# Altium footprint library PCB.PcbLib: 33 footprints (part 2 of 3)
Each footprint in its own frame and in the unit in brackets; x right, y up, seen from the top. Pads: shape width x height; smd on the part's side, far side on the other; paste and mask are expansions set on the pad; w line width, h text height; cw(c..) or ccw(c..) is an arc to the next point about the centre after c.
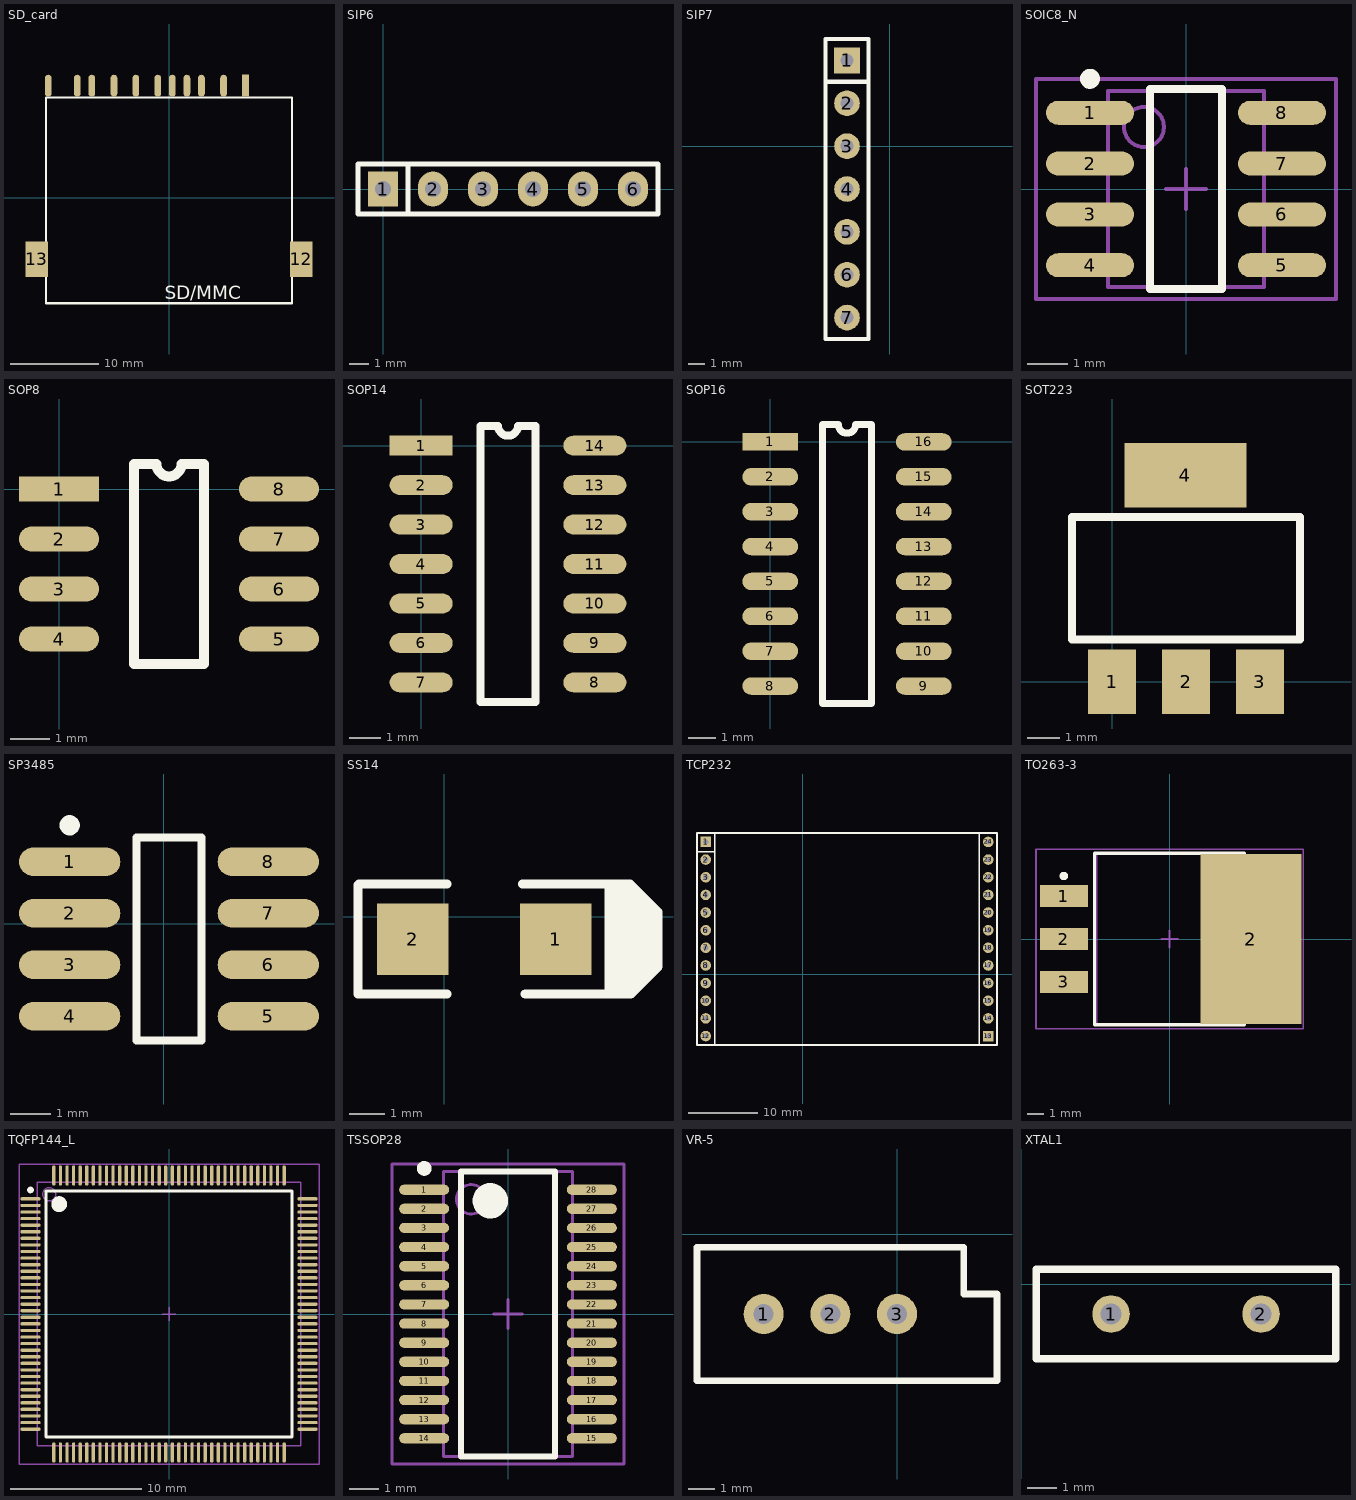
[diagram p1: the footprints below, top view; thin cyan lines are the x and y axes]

## SD_card [mil]
height 62.99
pads (13):
  oval 30x98.43 smd: 1(244,500) 2(145,500) 3(15,500) 3(80,500) 4(-50,500) 5(-148,500) 6(-246,500) 7(-345,500) 8(-410,500) 10(-540,500)
  rect 30x98.43 smd: 9(342,500)
  rect 100x160 smd: 12(590.55,-275.59) 13(-590.55,-275.59)
Top Overlay:
  lines w10: -550,-472.44 550,-472.44 550,447.56 -550,447.56 -550,-472.44
  text "SD/MMC" at -20,-455 h60

## SIP6 [mil]
pads (6):
  rect 60x70 hole 32: 1(0,0)
  oval 60x70 hole 32: 2(100,0) 3(200,0) 4(300,0) 5(400,0) 6(500,0)
Top Overlay:
  lines w10: 50,-50 50,50 ; -50,-50 550,-50 550,50 -50,50 -50,-50

## SIP7 [mil]
height 62.99
pads (7):
  rect 60x60 hole 30: 1(-100,200)
  round 60 hole 30: 2(-100,100) 3(-100,0) 4(-100,-100) 5(-100,-200) 6(-100,-300) 7(-100,-400)
Top Overlay:
  lines w10: -150,150 -50,150 ; -150,-450 -150,250 -50,250 -50,-450 -150,-450

## SOIC8_N [mm] "SOIC, 8-Leads, Body 4.9x3.9mm, Pitch 1.27mm, IPC Medium Density"
height 1.75
pads (8):
  oval 2.2x0.6 smd: 1(-2.4,1.905) 2(-2.4,0.635) 3(-2.4,-0.635) 4(-2.4,-1.905) 5(2.4,-1.905) 6(2.4,-0.635) 7(2.4,0.635) 8(2.4,1.905)
Top Overlay:
  circle w0.25: c-2.4,2.755 r0.125
  lines w0.2: -0.9,-2.5 0.9,-2.5 0.9,2.5 -0.9,2.5 -0.9,-2.5
Mechanical 13:
  circle w0.1: c-1.05,1.55 r0.5
  lines w0.1: -1.95,-2.45 1.95,-2.45 1.95,2.45 -1.95,2.45 -1.95,-2.45
Mechanical 15:
  lines w0.1: -0.5,0 0.5,0 ; 0,-0.5 0,0.5 ; -3.75,-2.75 3.75,-2.75 3.75,2.75 -3.75,2.75 -3.75,-2.75
3D body: height 1.75, standoff 0, extent -1.95,-2.45 1.95,2.45

## SOP8 [mil]
height 62.99
pads (8):
  rect 80x25 smd: 1(0,0)
  oval 80x25 smd: 2(0,-50) 3(0,-100) 4(0,-150) 5(220,-150) 6(220,-100) 7(220,-50) 8(220,0)
Top Overlay:
  lines w10: 75,-175 75,25 97.5,25 ccw(c110,25) 122.5,25 145,25 145,-175 75,-175

## SOP14 [mil]
height 62.99
pads (14):
  rect 80x25 smd: 1(0,0)
  oval 80x25 smd: 2(0,-50) 3(0,-100) 4(0,-150) 5(0,-200) 6(0,-250) 7(0,-300) 8(220,-300) 9(220,-250) 10(220,-200) 11(220,-150) 12(220,-100) 13(220,-50) 14(220,0)
Top Overlay:
  lines w10: 75,-325 75,25 97.5,25 ccw(c110,25) 122.5,25 145,25 145,-325 75,-325

## SOP16 [mil]
pads (16):
  rect 80x25 smd: 1(0,0)
  oval 80x25 smd: 2(0,-50) 3(0,-100) 4(0,-150) 5(0,-200) 6(0,-250) 7(0,-300) 8(0,-350) 9(220,-350) 10(220,-300) 11(220,-250) 12(220,-200) 13(220,-150) 14(220,-100) 15(220,-50) 16(220,0)
Top Overlay:
  lines w10: 75,-375 145,-375 145,25 122.5,25 cw(c110,25) 97.5,25 75,25 75,-375

## SOT223 [mil]
pads (4):
  rect 59x79 smd: 1(0,0) 2(90.55,0) 3(181.1,0)
  rect 150x79 smd: 4(89.88,253.54)
Top Overlay:
  lines w10: -49.45,52 -49.45,202 230.55,202 230.55,52 -49.45,52

## SP3485 [mm]
height 1.6
pads (8):
  oval 2.5x0.7 smd: 1(-2.323,1.524) 2(-2.323,0.254) 3(-2.323,-1.016) 4(-2.323,-2.286) 5(2.577,-2.286) 6(2.577,-1.016) 7(2.577,0.254) 8(2.577,1.524)
Top Overlay:
  circle w0.25: c-2.323,2.424 r0.125
  lines w0.2: -0.673,-2.881 -0.673,2.119 0.927,2.119 0.927,-2.881 -0.673,-2.881

## SS14 [mm]
pads (2):
  rect 2x2 smd: 1(3.111,-0.635) 2(-0.889,-0.635)
Top Overlay:
  rectangle: 5.461,-1.397 5.969,-1.016
  rectangle: 5.436,-1.245 5.969,0.127
  rectangle: 5.335,-1.751 5.737,0.361
  rectangle: 4.597,-1.93 5.49,0.606
  rectangle: 4.597,-2.108 5.258,0.889
  lines w0.254: -2.413,0.889 -2.413,-2.159 0.076,-2.159 ; -2.388,0.914 0.076,0.914 ; 2.184,0.914 4.597,0.914 5.131,0.914 5.182,0.914 5.944,0.152 5.969,0.127 5.969,-1.397 5.258,-2.108 5.207,-2.159 4.597,-2.159 ; 2.261,-2.159 4.597,-2.159 ; 4.597,0.889 4.597,-2.159 ; 5.373,0.723 5.373,0.398 5.373,0.19 5.542,0.36 5.609,0.36 5.969,0 ; 5.69,-1.473 5.69,-1.245

## TCP232 [mil]
height 62.99
pads (24):
  rect 60x60 hole 30: 1(-550,750) 13(1050,-350)
  round 60 hole 30: 2(-550,650) 3(-550,550) 4(-550,450) 5(-550,350) 6(-550,250) 7(-550,150) 8(-550,50) 9(-550,-50) 10(-550,-150) 11(-550,-250) 12(-550,-350) 14(1050,-250) 15(1050,-150) 16(1050,-50) 17(1050,50) 18(1050,150) 19(1050,250) 20(1050,350) 21(1050,450) 22(1050,550) 23(1050,650) 24(1050,750)
Top Overlay:
  lines w10: -600,695 -500,695 ; -500,-400 1000,-400 ; -500,-400 -600,-400 -600,800 -500,800 ; -500,-400 -500,800 ; -500,800 1000,800 ; 1000,-400 1000,800 ; 1000,-400 1100,-400 1100,800 1000,800

## TO263-3 [mm] "SOT223, 4-Leads, Body 10.2x14.4mm (max), Pitch 2.54mm, IPC Medium Density"
height 4.57
pads (4):
  rect 2.85x1.3 smd: 1(-6.275,2.54) 2(-6.275,0) 3(-6.275,-2.54)
  rect 6x10.1 smd: 2(4.826,0)
Top Overlay:
  circle w0.25: c-6.275,3.74 r0.125
  lines w0.2: -4.45,-5.08 4.45,-5.08 4.45,5.08 -4.45,5.08 -4.45,-5.08
Mechanical 13:
  lines w0.1: -4.32,-5.08 4.32,-5.08 4.32,5.08 -4.32,5.08 -4.32,-5.08
Mechanical 15:
  lines w0.1: -0.5,0 0.5,0 ; 0,-0.5 0,0.5 ; -7.925,-5.33 7.925,-5.33 7.925,5.33 -7.925,5.33 -7.925,-5.33
3D body: height 4.57, standoff 0.76, extent -4.32,-5.08 4.32,5.08

## TQFP144_L [mm] "Thin QFP, 144-Leads, Body 20x20mm, Pitch 0.5mm, IPC High Density"
height 1.6
pads (144):
  oval 1.55x0.25 smd: 1(-10.525,8.75) 2(-10.525,8.25) 3(-10.525,7.75) 4(-10.525,7.25) 5(-10.525,6.75) 6(-10.525,6.25) 7(-10.525,5.75) 8(-10.525,5.25) 9(-10.525,4.75) 10(-10.525,4.25) 11(-10.525,3.75) 12(-10.525,3.25) 13(-10.525,2.75) 14(-10.525,2.25) 15(-10.525,1.75) 16(-10.525,1.25) 17(-10.525,0.75) 18(-10.525,0.25) 19(-10.525,-0.25) 20(-10.525,-0.75) 21(-10.525,-1.25) 22(-10.525,-1.75) 23(-10.525,-2.25) 24(-10.525,-2.75) 25(-10.525,-3.25) 26(-10.525,-3.75) 27(-10.525,-4.25) 28(-10.525,-4.75) 29(-10.525,-5.25) 30(-10.525,-5.75) 31(-10.525,-6.25) 32(-10.525,-6.75) 33(-10.525,-7.25) 34(-10.525,-7.75) 35(-10.525,-8.25) 36(-10.525,-8.75) 73(10.525,-8.75) 74(10.525,-8.25) 75(10.525,-7.75) 76(10.525,-7.25) 77(10.525,-6.75) 78(10.525,-6.25) 79(10.525,-5.75) 80(10.525,-5.25) 81(10.525,-4.75) 82(10.525,-4.25) 83(10.525,-3.75) 84(10.525,-3.25) 85(10.525,-2.75) 86(10.525,-2.25) 87(10.525,-1.75) 88(10.525,-1.25) 89(10.525,-0.75) 90(10.525,-0.25) 91(10.525,0.25) 92(10.525,0.75) 93(10.525,1.25) 94(10.525,1.75) 95(10.525,2.25) 96(10.525,2.75) 97(10.525,3.25) 98(10.525,3.75) 99(10.525,4.25) 100(10.525,4.75) 101(10.525,5.25) 102(10.525,5.75) 103(10.525,6.25) 104(10.525,6.75) 105(10.525,7.25) 106(10.525,7.75) 107(10.525,8.25) 108(10.525,8.75)
  oval 0.25x1.55 smd: 37(-8.75,-10.525) 38(-8.25,-10.525) 39(-7.75,-10.525) 40(-7.25,-10.525) 41(-6.75,-10.525) 42(-6.25,-10.525) 43(-5.75,-10.525) 44(-5.25,-10.525) 45(-4.75,-10.525) 46(-4.25,-10.525) 47(-3.75,-10.525) 48(-3.25,-10.525) 49(-2.75,-10.525) 50(-2.25,-10.525) 51(-1.75,-10.525) 52(-1.25,-10.525) 53(-0.75,-10.525) 54(-0.25,-10.525) 55(0.25,-10.525) 56(0.75,-10.525) 57(1.25,-10.525) 58(1.75,-10.525) 59(2.25,-10.525) 60(2.75,-10.525) 61(3.25,-10.525) 62(3.75,-10.525) 63(4.25,-10.525) 64(4.75,-10.525) 65(5.25,-10.525) 66(5.75,-10.525) 67(6.25,-10.525) 68(6.75,-10.525) 69(7.25,-10.525) 70(7.75,-10.525) 71(8.25,-10.525) 72(8.75,-10.525) 109(8.75,10.525) 110(8.25,10.525) 111(7.75,10.525) 112(7.25,10.525) 113(6.75,10.525) 114(6.25,10.525) 115(5.75,10.525) 116(5.25,10.525) 117(4.75,10.525) 118(4.25,10.525) 119(3.75,10.525) 120(3.25,10.525) 121(2.75,10.525) 122(2.25,10.525) 123(1.75,10.525) 124(1.25,10.525) 125(0.75,10.525) 126(0.25,10.525) 127(-0.25,10.525) 128(-0.75,10.525) 129(-1.25,10.525) 130(-1.75,10.525) 131(-2.25,10.525) 132(-2.75,10.525) 133(-3.25,10.525) 134(-3.75,10.525) 135(-4.25,10.525) 136(-4.75,10.525) 137(-5.25,10.525) 138(-5.75,10.525) 139(-6.25,10.525) 140(-6.75,10.525) 141(-7.25,10.525) 142(-7.75,10.525) 143(-8.25,10.525) 144(-8.75,10.525)
Top Overlay:
  circle w0.25: c-10.525,9.425 r0.125
  circle w0.6: c-8.35,8.35 r0.3
  lines w0.2: -9.35,-9.35 -9.35,9.35 9.35,9.35 9.35,-9.35 -9.35,-9.35
Mechanical 13:
  circle w0.1: c-9.1,9.1 r0.5
  lines w0.1: -10,-10 -10,10 10,10 10,-10 -10,-10
Mechanical 15:
  lines w0.1: -0.5,0 0.5,0 ; 0,-0.5 0,0.5 ; -11.4,-11.4 -11.4,11.4 11.4,11.4 11.4,-11.4 -11.4,-11.4
3D body: height 1.6, standoff 0, extent -10,-10 10,10

## TSSOP28 [mm] "TSOP, 28-Leads, Body 9.7x4.4mm (max), Pitch 0.65mm, IPC Medium Density"
height 1.2
pads (28):
  oval 1.7x0.35 smd: 1(-2.85,4.225) 2(-2.85,3.575) 3(-2.85,2.925) 4(-2.85,2.275) 5(-2.85,1.625) 6(-2.85,0.975) 7(-2.85,0.325) 8(-2.85,-0.325) 9(-2.85,-0.975) 10(-2.85,-1.625) 11(-2.85,-2.275) 12(-2.85,-2.925) 13(-2.85,-3.575) 14(-2.85,-4.225) 15(2.85,-4.225) 16(2.85,-3.575) 17(2.85,-2.925) 18(2.85,-2.275) 19(2.85,-1.625) 20(2.85,-0.975) 21(2.85,-0.325) 22(2.85,0.325) 23(2.85,0.975) 24(2.85,1.625) 25(2.85,2.275) 26(2.85,2.925) 27(2.85,3.575) 28(2.85,4.225)
Top Overlay:
  circle w0.6: c-0.6,3.85 r0.3
  circle w0.25: c-2.85,4.95 r0.125
  lines w0.2: -1.6,-4.85 1.6,-4.85 1.6,4.85 -1.6,4.85 -1.6,-4.85
Mechanical 13:
  circle w0.1: c-1.25,3.9 r0.5
  lines w0.1: -2.2,-4.85 2.2,-4.85 2.2,4.85 -2.2,4.85 -2.2,-4.85
Mechanical 15:
  lines w0.1: -0.5,0 0.5,0 ; 0,-0.5 0,0.5 ; -3.95,-5.1 3.95,-5.1 3.95,5.1 -3.95,5.1 -3.95,-5.1
3D body: height 1.2, standoff 0.1, extent -2.2,-4.85 2.2,4.85

## VR-5 [mil]
pads (3):
  round 60 hole 30: 1(-200,-120) 2(-100,-120) 3(0,-120)
Top Overlay:
  lines w10: -300,-220 -300,-20 100,-20 100,-90 150,-90 150,-220 -300,-220

## XTAL1 [mil]
height 62.99
pads (2):
  round 50 hole 28: 1(120,-40) 2(320,-40)
Top Overlay:
  lines w10: 120,-50 120,-30 ; 320,-50 320,-30 ; 20,-100 20,20 420,20 420,-100 20,-100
